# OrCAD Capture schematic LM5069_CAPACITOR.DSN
size Custom
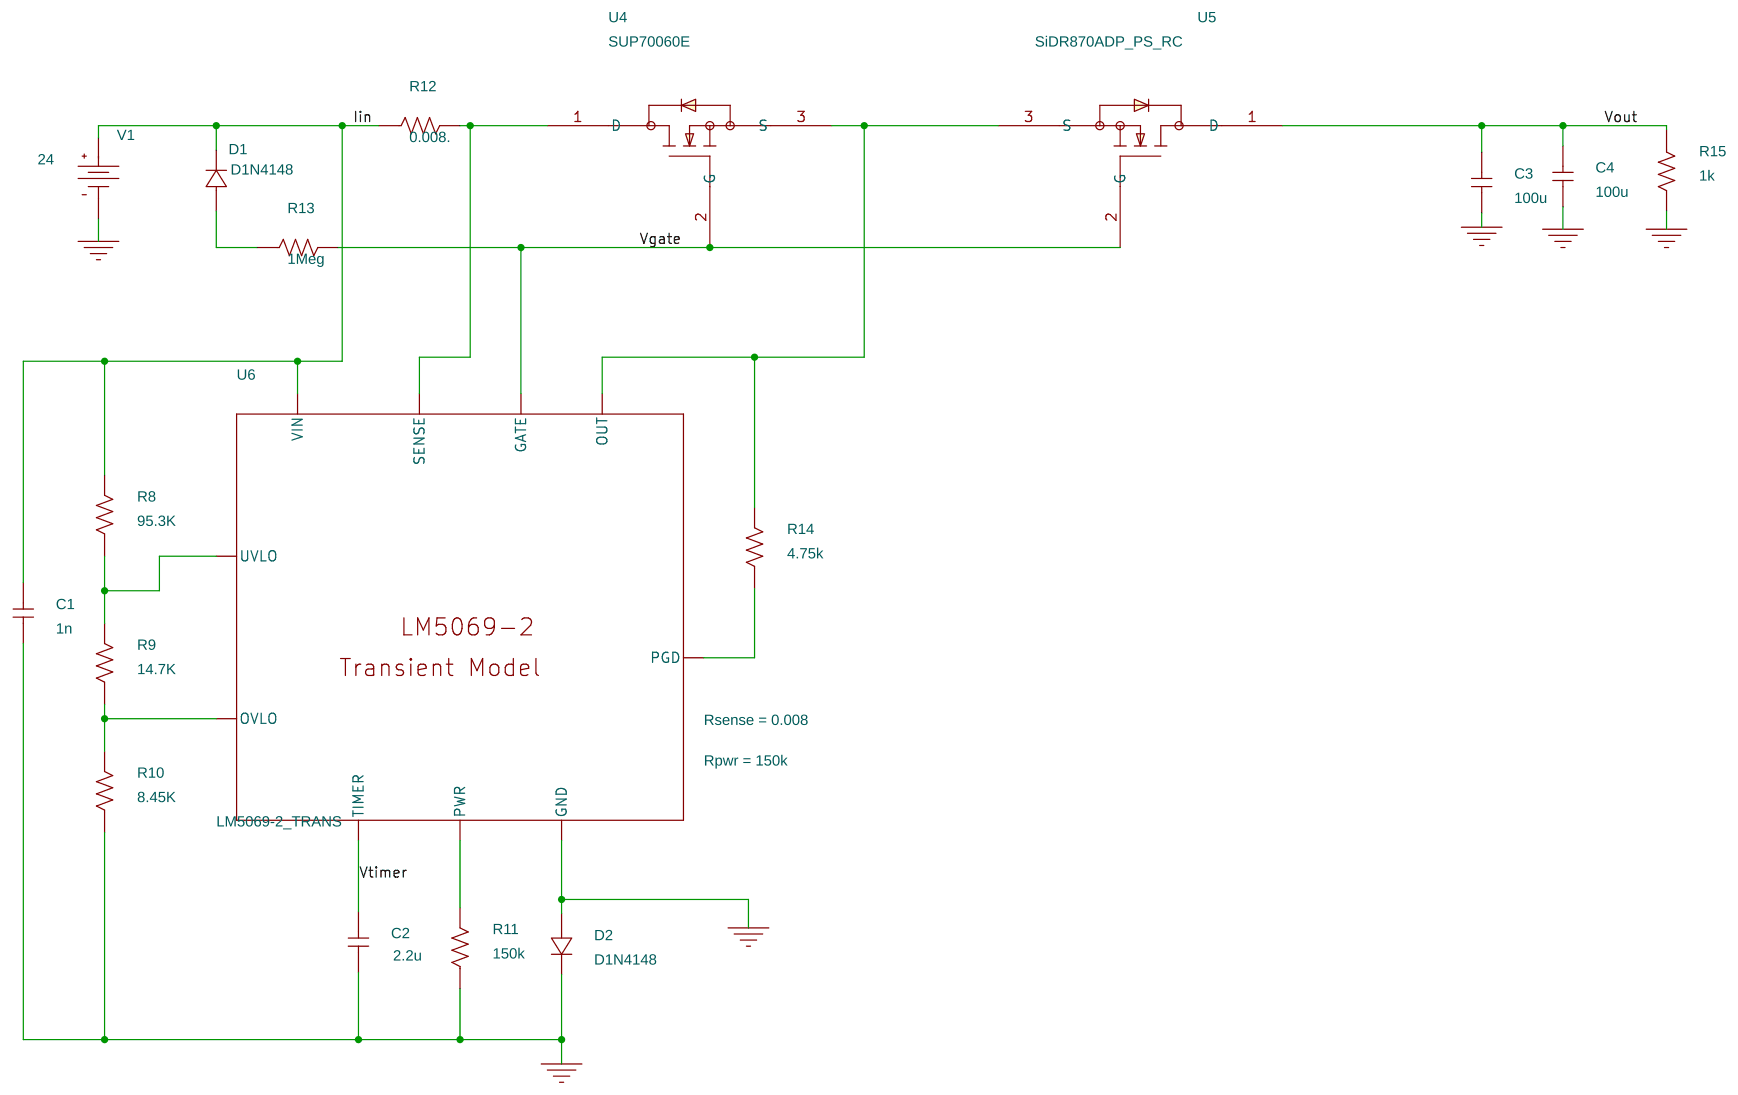
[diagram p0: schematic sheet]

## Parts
C1  1n  [RAD/CK05]
C2  2.2u  [RAD/CK05]
C3  100u  [RAD/CK05]
C4  100u  [RAD/CK05]
D1  D1N4148  [DO-35]
D2  D1N4148  [DO-35]
R8  95.3K  [AX/RC05]
R9  14.7K  [AX/RC05]
R10  8.45K  [AX/RC05]
R11  150k  [AX/RC05]
R12  0.008.  [AX/RC05]
R13  1Meg  [AX/RC05]
R14  4.75k  [AX/RC05]
R15  1k  [AX/RC05]
U4  SUP70060E
U5  SiDR870ADP_PS_RC
U6  LM5069-2_TRANS
V1  VDC

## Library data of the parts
C1-C4 = C
D1 D2 = 1N4148
R8-R15 = R
U4 = SUP70060E
U5 = SiDR870ADP_PS_RC
U6 = LM5069-2_TRANS: Rpwr: 150k; Rsense: 0.008
V1 = VDC: DC: 24

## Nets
0: C1.1 C2.1 C3.1 C4.1 D2.1 D2.2 R10.1 R11.1 R15.2 U6.GND V1.1(-)
Iin: C1.2 D1.2 R8.2 R12.1 U6.VIN V1.0(+)
Vgate: R13.2 U4.2(G) U5.2(G) U6.GATE
Vout: C3.2 C4.2 R15.1 U5.1(D)
Vtimer : C2.2 U6.TIMER
N128090: R8.1 R9.2 U6.UVLO
N128094: R9.1 R10.2 U6.OVLO
N135483: R11.2 U6.PWR
N136012: D1.1 R13.1
N136091: R12.2 U4.1(D) U6.SENSE
N136506: R14.2 U4.3(S) U5.3(S) U6.OUT
N136544: R14.1 U6.PGD
